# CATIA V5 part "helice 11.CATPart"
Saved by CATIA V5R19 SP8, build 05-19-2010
Part number: helice 11
Bounding box of the stored display mesh (mm): x -17.715 to 17.321, y -30 to 195, z -10.683 to 20
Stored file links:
  G:\EU_thinkMotion\CFAO_2010\MMS_groupe2\MMS_groupe2\A reprendre\splanchenault\Planchenault\helice 11.CATPart
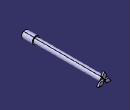
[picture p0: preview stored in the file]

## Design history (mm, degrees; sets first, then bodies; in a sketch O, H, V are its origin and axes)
Body1 (main body)
  Sketch1 on yz-plane, origin (0, 0, 0), H (0, 1, 0), V (0, 0, 1)
    line L1 (0, 0) -> (-30, 0)
    line L2 (-30, 0) -> (-30, 10)
    line L3 (-30, 10) -> (0, 10)
    line L4 (0, 10) -> (0, 7.5)
    line L5 (0, 7.5) -> (190, 7.5)
    line L6 (190, 7.5) -> (190, 0)
    line L7 (190, 0) -> (0, 0)
    length L6 = 7.5
    length L2 = 10
    length L3 = 30
    length L5 = 190
    distance V L2 = 30
    horizontal: L1 H, L3 H, L5 H, L7 H
    vertical: L2 V, L4 V, L6 V
  Shaft1: profile Sketch1, axis Sketch1.L1, angle 360
  Sketch2 on face of Shaft1 from Sketch1.L6, origin (0, 190, 0), H (-1, 0, 0), V (0, 0, 1)
    construction line L1 (27.3861, -15.8114) -> (-27.3861, 15.8114)
    axis line L2 (-25.1162, -14.9563) -> (27.5134, 15.4294)
    line L3 (0, 0) -> (5.7735, 10)
    point P5 (5.7735, 10)
    line L4 (5.7735, 10) -> (0, 20)
    point P6 (0, 20)
    line L5 (0, 20) -> (-5.7735, 10)
    point P7 (-5.7735, 10)
    line L6 (-5.7735, 10) -> (0, 0)
    point P8 (-11.547, 0)
    point P9 (-17.3205, -10)
    line L7 (-17.3205, -10) -> (-11.547, 0)
    point P10 (-5.7735, -10)
    line L8 (-5.7735, -10) -> (-17.3205, -10)
    point P11 (0, 0)
    line L9 (0, 0) -> (-5.7735, -10)
    line L10 (-11.547, 0) -> (0, 0)
    point P12 (6.168, -10.6832)
    point P13 (17.715, -10.6832)
    line L11 (17.715, -10.6832) -> (6.168, -10.6832)
    point P14 (11.9415, -0.6832)
    line L12 (11.9415, -0.6832) -> (17.715, -10.6832)
    point P15 (0.3945, -0.6832)
    line L13 (0.3945, -0.6832) -> (11.9415, -0.6832)
    line L14 (6.168, -10.6832) -> (0.3945, -0.6832)
    angle L1 V = 60
    angle L2 V = 60
    perpendicularity: L3 L1, L4 L2
    coincidence: P6 V, O P11
    parallelism: L5 L3
    symmetry: P7 P8 L1, P6 P9 L1, L5 L7 L1, P5 P10 L1, L4 L8 L1, O P11 L1, L3 L9 L1, L6 L10 L1, P7 P12 L2, P6 P13 L2, L5 L11 L2, P5 P14 L2, L4 L12 L2, O P15 L2, L3 L13 L2, L6 L14 L2
  Pad1: profile Sketch2, direction (0, 1, 0), length 5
